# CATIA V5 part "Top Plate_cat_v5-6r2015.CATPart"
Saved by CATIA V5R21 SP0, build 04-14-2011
Part number: Top Plate
Bounding box of the stored display mesh (mm): x -125 to 125, y 0 to 150, z 180 to 210
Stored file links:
  E:\cadcim\Projects\CATIA Resources\CATIA V5-6R2014_partfiles_kavita\Tutorials\c12_catia_v5_6r2014_tut\c12tut2\Top Plate_cat_v5-6r2014.CATPart
  C:\Users\Ashutosh\Desktop\Press Tool Base\Press Tool Base.CATProduct
  D:\CATIA V5R21 E-RESOURCES\CATIA-V5R21\catia-v5r21-Tut\c12-catia-v5r21-tut\c12-catia-v5r21-tut02\Bush.CATPart
  D:\CATIA V5R21 E-RESOURCES\CATIA-V5R21\catia-v5r21-Tut\c12-catia-v5r21-tut\c12-catia-v5r21-tut02\Bottom Plate.CATPart
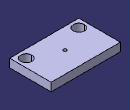
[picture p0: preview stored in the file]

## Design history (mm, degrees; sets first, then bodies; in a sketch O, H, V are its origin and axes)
Set1
  DatumSurface1: linked copy from another document
  DatumCurve1 to DatumCurve5: linked copy from another document
Body1 (main body)
  Sketch1 on face of DatumSurface1, origin (0, 0, 210), H (1, 0, 0), V (0, 1, 0)
    projected line E1 (-125, 0) -> (125, 0) from edge of DatumCurve1
    point P1 (-125, 0)
    point P2 (125, 0)
    projected line E2 (125, 0) -> (125, 150) from edge of DatumCurve2
    point P3 (125, 0)
    point P4 (125, 150)
    projected line E3 (125, 150) -> (-125, 150) from edge of DatumCurve3
    point P5 (125, 150)
    point P6 (-125, 150)
    projected line E4 (-125, 150) -> (-125, 0) from edge of DatumCurve4
    point P7 (-125, 150)
    point P8 (-125, 0)
    projected circle E5 centre (95, 30) radius 20 from edge of DatumCurve5
    circle A1 centre (-95, 30) radius 20
    symmetry: E5 A1 V
    coincidence: P1 P8, P2 P3, P4 P5, P6 P7
  Pad1: profile Sketch1, direction (0, 0, -1), length 30
  Sketch2 on face of Pad1, origin (0, 0, 210), H (1, 0, 0), V (0, 1, 0)
    circle A1 centre (0, 75) radius 6
    point P1 (0, 75)
    reference projected line E1 (-125, 0) -> (125, 0) from edge [face of Pad1 | face of Pad1]
    radius A1 = 6
    distance E1 P1 = 75
    coincidence: P1 V
  Pocket1: profile Sketch2, direction (0, 0, -1), through (limit type 6)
